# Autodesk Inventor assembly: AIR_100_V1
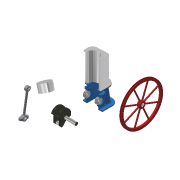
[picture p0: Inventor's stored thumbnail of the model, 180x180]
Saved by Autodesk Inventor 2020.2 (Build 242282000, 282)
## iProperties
Created: 2014-10
Part Number: AIR_100_V1
Document SubType Name: Assembly
Designer: F.Stasiak
Catalog Web Link: www.expertbooks.pl
Manager: www.cadconsulting.pl
Company: Fabian Stasiak CAD Consulting
Author: F.Stasiak
Subject: Zbiór ćwiczeń. Autodesk Inventor 2020. Kurs Professional
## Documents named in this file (11)
- C:\2020_Kurs_Professional\R3 Dynamika\AIR_100_V1.iam
- C:\2020_Kurs_Professional\R3 Dynamika\Komponenty_dyn\Korpus_AIR_01.ipt
- C:\2020_Kurs_Professional\R3 Dynamika\Komponenty_dyn\Wał_AIR_100.ipt
- C:\2020_Kurs_Professional\R3 Dynamika\Komponenty_dyn\Korbowód_AIR_100.ipt
- C:\2020_Kurs_Professional\R3 Dynamika\Komponenty_dyn\Cylinder_AIR_100.ipt
- C:\2020_Kurs_Professional\R3 Dynamika\Komponenty_dyn\Koło_AIR_100.ipt
- C:\2020_Kurs_Professional\R3 Dynamika\AIR_100\Design Accelerator\Łożysko2.iam
- C:\2020_Kurs_Professional\R3 Dynamika\AIR_100\Design Accelerator\Łożysko3.iam
- C:\2020_Kurs_Professional\R3 Dynamika\Komponenty_dyn\Sworzeń_AIR_100.ipt
- C:\2020_Kurs_Professional\R3 Dynamika\Komponenty_dyn\Tłok_AIR_100.ipt
- C:\2020_Kurs_Professional\R3 Dynamika\Komponenty_dyn\Stopka_AIR_100.ipt
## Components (10 placed, 9 different names)
1. Korpus_AIR_01:1
2. Cylinder_AIR_100:1
3. Wał_AIR_100:1
4. Korbowód_AIR_100:1 — Wstaw:1, Wstaw:2
5. Stopka_AIR_100:1 — Wstaw:1, Wstaw:2
6. Sworzeń_AIR_100:1 — Zestawiający:1, Równoległy:1
7. Tłok_AIR_100:1 — Zestawiający:1, Równoległy:1
8. Koło_AIR_100:1
9. Łożysko:1 [sub-assembly]
10. Łożysko:2 [sub-assembly]
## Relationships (4: Insert 2, Mate 1, Flush 1)
- Wstaw:1 [Insert]: Korbowód_AIR_100:1 ↔ Stopka_AIR_100:1
- Wstaw:2 [Insert]: Korbowód_AIR_100:1 ↔ Stopka_AIR_100:1
- Zestawiający:1 [Mate]: Sworzeń_AIR_100:1 ↔ Tłok_AIR_100:1
- Równoległy:1 [Flush]: Sworzeń_AIR_100:1 ↔ Tłok_AIR_100:1
